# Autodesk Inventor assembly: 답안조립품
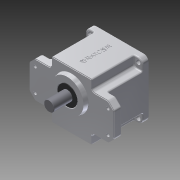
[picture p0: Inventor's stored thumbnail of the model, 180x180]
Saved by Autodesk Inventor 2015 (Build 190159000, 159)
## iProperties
Created: 2016-02
Part Number: 답안조립품
Document SubType Name: Assembly
Designer: Administrator
Author: Administrator
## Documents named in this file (10)
- C:\Users\Administrator\Desktop\460209V1006\답안조립품.iam
- C:\Users\Administrator\Desktop\460209V1006\본체.ipt
- C:\Users\Administrator\Desktop\460209V1006\커버.ipt
- C:\Users\Administrator\Desktop\460209V1006\오일실 17 32 8.ipt
- C:\Users\Administrator\Desktop\460209V1006\오일실 8 22 7.ipt
- C:\Users\Administrator\Desktop\460209V1006\베어링 608.ipt
- C:\Users\Administrator\Desktop\460209V1006\메인축.ipt
- C:\Users\Administrator\Desktop\460209V1006\서브축.ipt
- C:\Users\Administrator\Desktop\460209V1006\베어링 6003.ipt
- C:\Users\Administrator\Desktop\460209V1006\볼트 M4 x 10.ipt
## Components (2 placed, 1 different names)
1. ISO 4762 M4 x 10:1 — Insert:1
2. ISO 4762 M4 x 10:2 — Insert:2
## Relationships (2: Insert 2)
- Insert:1: ISO 4762 M4 x 10:1
- Insert:2: ISO 4762 M4 x 10:2
